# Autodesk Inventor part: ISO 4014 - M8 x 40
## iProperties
Comments: To add or edit properties for Autodesk Inventor files, use iProperties.
Created: 2004-08
Part Number: ISO 4014 - M8 x 40
Vendor: Autodesk Inc.
Document SubType Name: Modeling
Designer: John Blackburn
Material: Default
Description: Hex-Head Bolt
Standard: ISO 4014
Alert: To add or edit properties for Autodesk Inventor files, use iProperties.
Control State: 0
Master: False
Checked Out: False
Shininess: 64.0
Length Units: 11269
Angle Units: 11279
Time Units: 11290
Mass Units: 11283
Length Display Precision: 3
Angle Display Precision: 2
Compacted: True
EGR: 1
Density: 0.0
Volumn: 0.0
Area: 0.0
PropertySet Name: Model Information
Author: John Blackburn
Revision Number: 8
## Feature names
1. Body [Revolution]
2. Head [Extrusion]
3. Chamfer1 [Revolution]
4. Chamfer2
